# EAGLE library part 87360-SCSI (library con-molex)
CONNECTOR input/output 3 in 1 combo connector wide SCSI, 2.00 mm, power, right angle
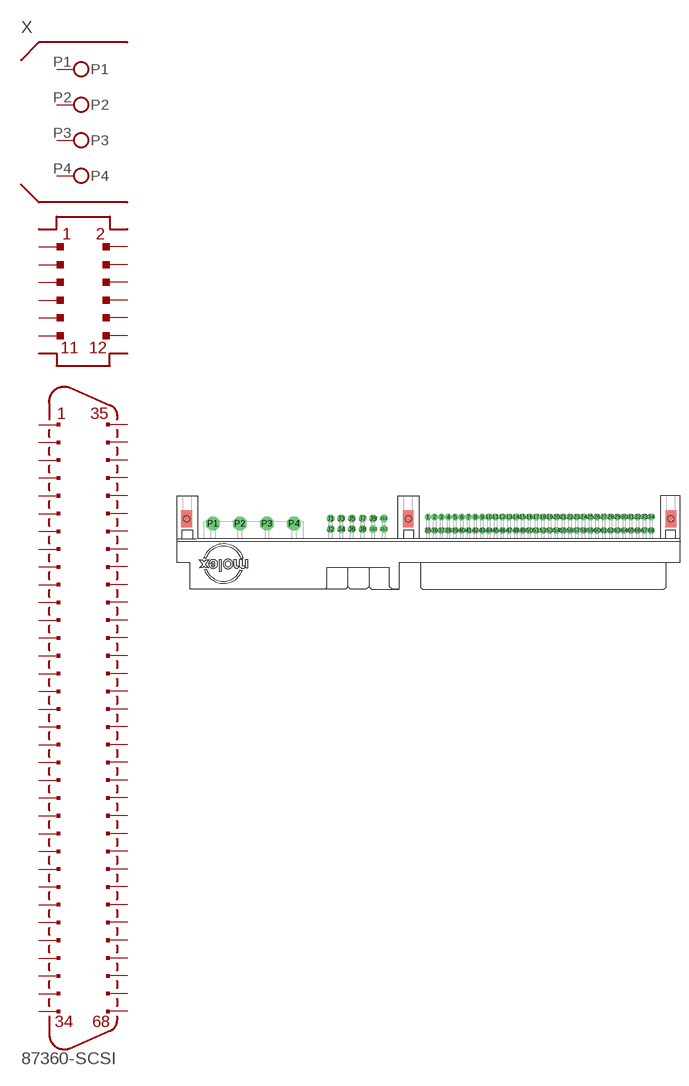
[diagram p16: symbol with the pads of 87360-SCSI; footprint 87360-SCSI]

Designator prefix X

## 87360-SCSI (OC_FARNELL: unknown; OC_NEWARK: unknown)  [87360-SCSI]
1  1  pas
2  2  pas
3  3  pas
4  4  pas
5  5  pas
6  6  pas
7  7  pas
8  8  pas
9  9  pas
10  10  pas
11  11  pas
12  12  pas
13  13  pas
14  14  pas
15  15  pas
16  16  pas
17  17  pas
18  18  pas
19  19  pas
20  20  pas
21  21  pas
22  22  pas
23  23  pas
24  24  pas
25  25  pas
26  26  pas
27  27  pas
28  28  pas
29  29  pas
30  30  pas
31  31  pas
32  32  pas
33  33  pas
34  34  pas
35  35  pas
36  36  pas
37  37  pas
38  38  pas
39  39  pas
40  40  pas
41  41  pas
42  42  pas
43  43  pas
44  44  pas
45  45  pas
46  46  pas
47  47  pas
48  48  pas
49  49  pas
50  50  pas
51  51  pas
52  52  pas
53  53  pas
54  54  pas
55  55  pas
56  56  pas
57  57  pas
58  58  pas
59  59  pas
60  60  pas
61  61  pas
62  62  pas
63  63  pas
64  64  pas
65  65  pas
66  66  pas
67  67  pas
68  68  pas
J1  J1  pas
J2  J2  pas
J3  J3  pas
J4  J4  pas
J5  J5  pas
J6  J6  pas
J7  J7  pas
J8  J8  pas
J9  J9  pas
J10  J10  pas
J11  J11  pas
J12  J12  pas
P1  P1  pas
P2  P2  pas
P3  P3  pas
P4  P4  pas

## Footprint 87360-SCSI (pad centres in mm)
CONNECTOR input/output 3 in 1 combo connector wide SCSI, 2.00 mm, power, right angle
drill 0.7 pad 1.016 octagon: 1 0,1.27; 2 1.27,1.27; 3 2.54,1.27; 4 3.81,1.27; 5 5.08,1.27; 6 6.35,1.27; 7 7.62,1.27; 8 8.89,1.27; 9 10.16,1.27; 10 11.43,1.27; 11 12.7,1.27; 12 13.97,1.27; 13 15.24,1.27; 14 16.51,1.27; 15 17.78,1.27; 16 19.05,1.27; 17 20.32,1.27; 18 21.59,1.27; 19 22.86,1.27; 20 24.13,1.27; 21 25.4,1.27; 22 26.67,1.27; 23 27.94,1.27; 24 29.21,1.27; 25 30.48,1.27; 26 31.75,1.27; 27 33.02,1.27; 28 34.29,1.27; 29 35.56,1.27; 30 36.83,1.27; 31 38.1,1.27; 32 39.37,1.27; 33 40.64,1.27; 34 41.91,1.27; 35 0,-1.27; 36 1.27,-1.27; 37 2.54,-1.27; 38 3.81,-1.27; 39 5.08,-1.27; 40 6.35,-1.27; 41 7.62,-1.27; 42 8.89,-1.27; 43 10.16,-1.27; 44 11.43,-1.27; 45 12.7,-1.27; 46 13.97,-1.27; 47 15.24,-1.27; 48 16.51,-1.27; 49 17.78,-1.27; 50 19.05,-1.27; 51 20.32,-1.27; 52 21.59,-1.27; 53 22.86,-1.27; 54 24.13,-1.27; 55 25.4,-1.27; 56 26.67,-1.27; 57 27.94,-1.27; 58 29.21,-1.27; 59 30.48,-1.27; 60 31.75,-1.27; 61 33.02,-1.27; 62 34.29,-1.27; 63 35.56,-1.27; 64 36.83,-1.27; 65 38.1,-1.27; 66 39.37,-1.27; 67 40.64,-1.27; 68 41.91,-1.27
drill 0.9 octagon: J1 -18.28,1; J2 -18.28,-1; J3 -16.28,1; J4 -16.28,-1; J5 -14.28,1; J6 -14.28,-1; J7 -12.28,1; J8 -12.28,-1; J9 -10.28,1; J10 -10.28,-1; J11 -8.28,1; J12 -8.28,-1
drill 1 pad 2.54 octagon: P1 -40.38,0; P2 -35.3,0; P3 -30.22,0; P4 -25.14,0
hole 1.14 at -3.685,0.92
hole 1.14 at 45.595,0.92
hole 1.14 at -45.295,0.92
